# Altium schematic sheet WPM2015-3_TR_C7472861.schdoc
size 127 x 101 mm
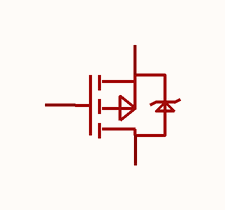
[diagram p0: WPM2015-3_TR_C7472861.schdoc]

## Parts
Q?  wpm2015-3/tr_c7472861  [SOT-23-3_L2.9-W1.3-P1.90-LS2.4-BR]  (value not drawn)

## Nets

Not connected (* = marked no-connect by the designer): Q? 1(G) 2(S) 3(D)

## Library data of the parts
Q? = wpm2015-3/tr_c7472861: 漏源电压(Vdss):20V;连续漏极电流(Id):2.8A;导通电阻(RDS(on)):80mΩ@2.5V,2A;耗散功率(Pd):1.25W;阈值电压(Vgs(th)):450mV;; Manufacturer: TECH PUBLIC(台舟); AddInBom: yes; ModelId: c62791f0466c4ae2a892c056b845b0ca; ModelName: SOT-23-3P_L2.9-W1.3-H1.0-LS2.4-P0.95; ModelTransform: 98.425,114.173,0,180,0,0,0.0005,-0.0005,0; Drain to Source Voltage: 20V; Current - Continuous Drain(Id): 2.8A; Pd - Power Dissipation: 1.25W; Gate Threshold Voltage (Vgs(th)): 450mV; Gate Charge(Qg): 9.6nC@4.5V; Input Capacitance(Ciss): 1.16nF; Reverse Transfer Capacitance (Crss@Vds): 125pF; Output Capacitance(Coss): 210pF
